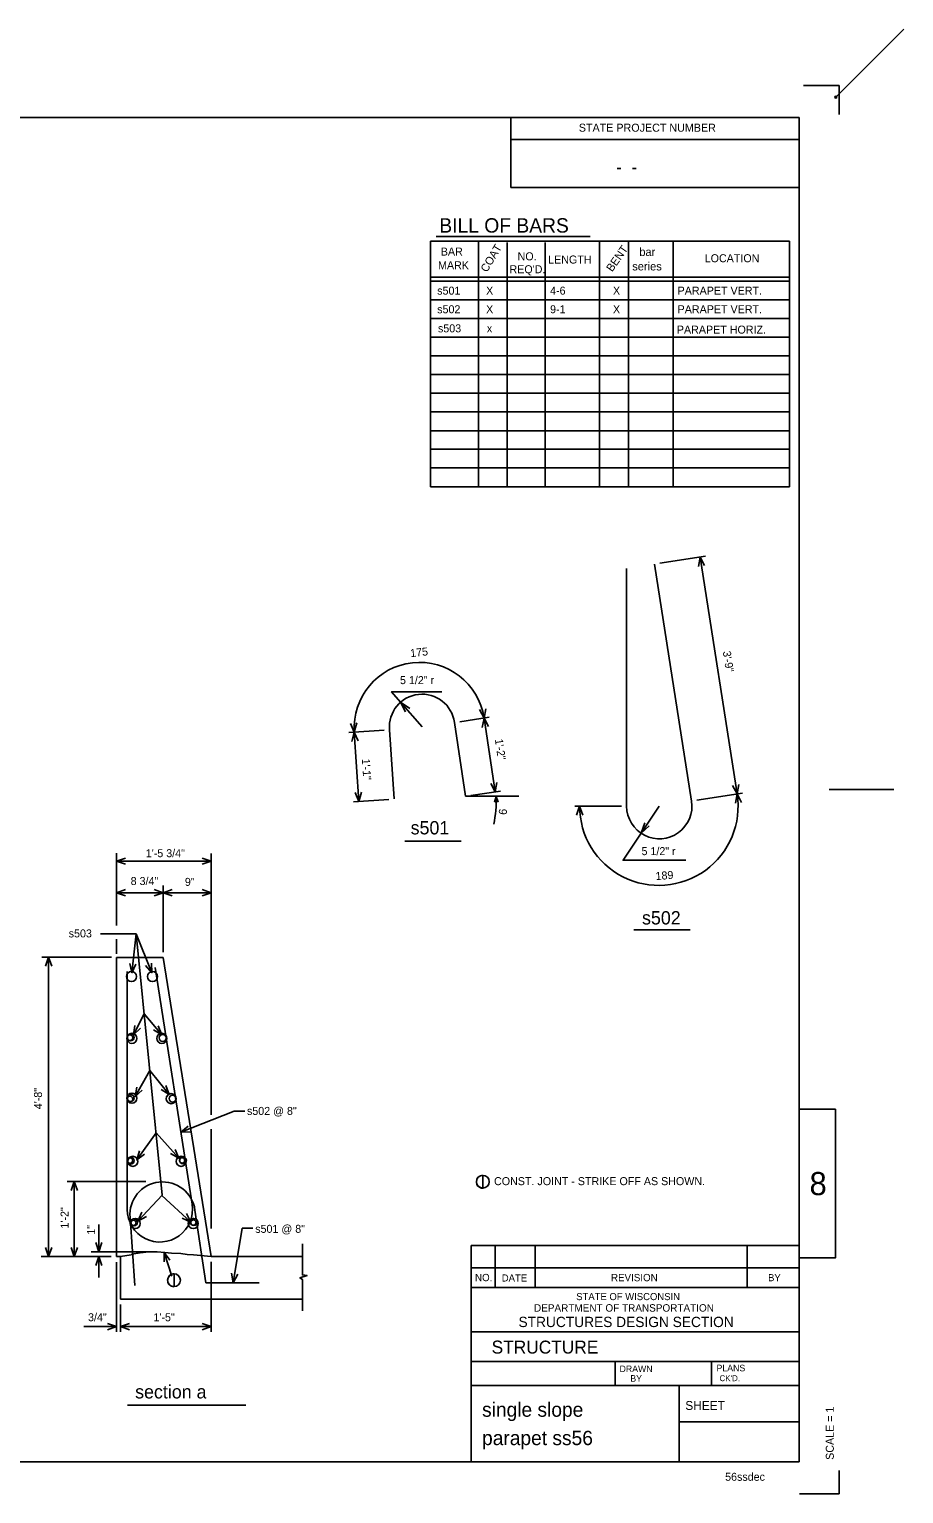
# Model space of a CAD drawing. Extents: x -38.4 to -2.2, y 84.9 to 109.4.
# Drawn here: x -15.84 to -2.17, y 85.97 to 108.85 of the extents above; entities that cross this region are included whole.
import ezdxf

# ---------------------------------------------------------------- set-up
doc = ezdxf.new("R2010")
doc.units = 0
for name, color, linetype in [('Default', 7, 'Continuous'), ('Level 1', 7, 'Continuous'), ('Level 2', 7, 'Continuous'), ('Level 37', 7, 'Continuous'), ('Level 49', 7, 'Continuous')]:
    doc.layers.add(name, color=color, linetype=linetype)

msp = doc.modelspace()

# ---------------------------------------------------------------- linework, layer by layer
at = {"layer": 'Default'}
for p, q in [((-14.473, 94.846), (-14.473, 95.978)), ((-14.473, 95.851), (-12.994, 95.851)), ((-12.994, 94.526), (-12.994, 95.97)), ((-13.744, 94.428), (-13.744, 95.471)), ((-14.473, 95.358), (-13.744, 95.358)), ((-13.744, 95.358), (-12.994, 95.358)), ((-14.168, 94.719), (-14.722, 94.719)), ((-14.232, 94.11), (-14.168, 94.719)), ((-14.168, 94.719), (-13.759, 90.637)), ((-14.168, 94.719), (-13.919, 94.11)), ((-12.994, 91.891), (-12.994, 94.809)), ((-14.473, 94.428), (-14.473, 94.634)), ((-14.473, 94.407), (-14.473, 94.617)), ((-14.55, 94.355), (-15.639, 94.355)), ((-15.533, 89.678), (-15.533, 94.355)), ((-14.473, 94.345), (-13.744, 94.345)), ((-14.473, 94.345), (-14.473, 89.678)), ((-12.994, 89.678), (-13.744, 94.345)), ((-14.304, 94.126), (-14.304, 90.412)), ((-13.291, 90.492), (-13.869, 94.193)), ((-14.206, 93.138), (-14.043, 93.469)), ((-14.043, 93.469), (-13.767, 93.138)), ((-14.181, 92.175), (-13.954, 92.581)), ((-13.954, 92.581), (-13.649, 92.209)), ((-12.633, 91.949), (-13.467, 91.617)), ((-12.466, 91.949), (-12.633, 91.949)), ((-14.156, 91.186), (-13.856, 91.609)), ((-13.856, 91.609), (-13.497, 91.212)), ((-12.994, 90.113), (-12.994, 91.664)), ((-14.017, 90.847), (-15.245, 90.847)), ((-15.133, 89.678), (-15.133, 90.847)), ((-8.748, 90.743), (-8.748, 90.943)), ((-8.748, 90.743), (-8.748, 90.943)), ((-13.759, 90.637), (-14.139, 90.231)), ((-13.311, 90.214), (-13.763, 90.632)), ((-13.078, 89.267), (-13.248, 90.4)), ((-14.75, 89.752), (-14.75, 90.178)), ((-14.189, 89.226), (-14.262, 90.286)), ((-12.509, 90.121), (-12.652, 89.267)), ((-12.342, 90.121), (-12.509, 90.121)), ((-14.557, 89.678), (-15.649, 89.678)), ((-15.213, 89.678), (-15.05, 89.678)), ((-13.943, 89.752), (-14.871, 89.752)), ((-14.75, 89.349), (-14.75, 89.678)), ((-14.473, 89.678), (-14.411, 89.678)), ((-14.411, 89.678), (-14.411, 89.011)), ((-13.611, 89.371), (-13.727, 89.741)), ((-11.568, 89.678), (-12.994, 89.678)), ((-14.473, 89.586), (-14.473, 88.498)), ((-12.994, 89.595), (-12.994, 88.498)), ((-13.573, 89.204), (-13.573, 89.405)), ((-13.078, 89.267), (-12.244, 89.267)), ((-14.411, 89.011), (-11.568, 89.011)), ((-14.411, 88.928), (-14.411, 88.498)), ((-14.473, 88.581), (-14.982, 88.581)), ((-14.411, 88.581), (-12.994, 88.581)), ((-14.302, 87.356), (-12.451, 87.356))]:
    msp.add_line(p, q, dxfattribs=at)
for points in [[(-14.333, 95.803), (-14.473, 95.851), (-14.333, 95.9)], [(-13.135, 95.9), (-12.994, 95.851), (-13.135, 95.803)], [(-14.333, 95.309), (-14.473, 95.358), (-14.333, 95.407)], [(-13.885, 95.407), (-13.744, 95.358), (-13.885, 95.309)], [(-13.603, 95.309), (-13.744, 95.358), (-13.603, 95.407)], [(-13.135, 95.407), (-12.994, 95.358), (-13.135, 95.309)], [(-15.582, 94.214), (-15.533, 94.355), (-15.484, 94.214)], [(-14.169, 94.245), (-14.232, 94.11), (-14.265, 94.256)], [(-13.927, 94.259), (-13.919, 94.11), (-14.018, 94.222)], [(-14.1, 93.243), (-14.206, 93.138), (-14.187, 93.286)], [(-13.82, 93.278), (-13.767, 93.138), (-13.895, 93.216)], [(-14.07, 92.274), (-14.181, 92.175), (-14.155, 92.322)], [(-13.7, 92.349), (-13.649, 92.209), (-13.776, 92.287)], [(-13.318, 91.624), (-13.467, 91.617), (-13.354, 91.714)], [(-14.035, 91.273), (-14.156, 91.186), (-14.114, 91.329)], [(-13.555, 91.349), (-13.497, 91.212), (-13.627, 91.284)], [(-15.182, 90.706), (-15.133, 90.847), (-15.084, 90.706)], [(-14.007, 90.301), (-14.139, 90.231), (-14.078, 90.367)], [(-13.381, 90.346), (-13.311, 90.214), (-13.447, 90.274)], [(-13.355, 90.297), (-13.311, 90.214), (-13.396, 90.252)], [(-15.484, 89.819), (-15.533, 89.678), (-15.582, 89.819)], [(-15.084, 89.819), (-15.133, 89.678), (-15.182, 89.819)], [(-14.701, 89.893), (-14.75, 89.752), (-14.798, 89.893)], [(-14.798, 89.537), (-14.75, 89.678), (-14.701, 89.537)], [(-14.411, 89.678), (-14.245, 89.7), (-14.233, 89.712), (-14.101, 89.734), (-13.966, 89.752), (-13.837, 89.749), (-13.717, 89.737), (-13.616, 89.728), (-13.469, 89.725), (-13.371, 89.71), (-13.269, 89.7), (-12.994, 89.678)], [(-13.731, 89.592), (-13.727, 89.741), (-13.638, 89.621)], [(-11.568, 88.826), (-11.568, 89.319), (-11.609, 89.341), (-11.497, 89.382), (-11.568, 89.388), (-11.568, 89.874)], [(-12.58, 89.398), (-12.652, 89.267), (-12.676, 89.414)], [(-14.614, 88.63), (-14.473, 88.581), (-14.614, 88.533)], [(-14.27, 88.533), (-14.411, 88.581), (-14.27, 88.63)], [(-13.135, 88.63), (-12.994, 88.581), (-13.135, 88.533)]]:
    msp.add_lwpolyline(points, dxfattribs=at)
for points in [[(-8.748, 90.744), (-8.748, 90.943), (-8.748, 90.944), (-8.767, 90.943), (-8.789, 90.937), (-8.807, 90.927), (-8.826, 90.91), (-8.837, 90.895), (-8.846, 90.874), (-8.851, 90.849), (-8.849, 90.825), (-8.844, 90.807), (-8.831, 90.783), (-8.818, 90.77), (-8.802, 90.757), (-8.785, 90.75), (-8.77, 90.746), (-8.762, 90.744)], [(-8.748, 90.744), (-8.748, 90.943), (-8.748, 90.944), (-8.767, 90.943), (-8.789, 90.937), (-8.807, 90.927), (-8.826, 90.91), (-8.837, 90.895), (-8.846, 90.874), (-8.851, 90.849), (-8.849, 90.825), (-8.844, 90.807), (-8.831, 90.783), (-8.818, 90.77), (-8.802, 90.757), (-8.785, 90.75), (-8.77, 90.746), (-8.762, 90.744)], [(-13.573, 89.205), (-13.573, 89.405), (-13.573, 89.405), (-13.592, 89.404), (-13.614, 89.399), (-13.632, 89.388), (-13.651, 89.372), (-13.662, 89.356), (-13.671, 89.335), (-13.676, 89.31), (-13.673, 89.286), (-13.669, 89.269), (-13.656, 89.245), (-13.643, 89.232), (-13.627, 89.219), (-13.61, 89.212), (-13.595, 89.207), (-13.586, 89.206)]]:
    msp.add_lwpolyline(points, close=True, dxfattribs=at)
for centre, radius in [((-14.239, 94.049), 0.0788), ((-13.91, 94.049), 0.0788), ((-14.232, 93.084), 0.0788), ((-14.253, 93.099), 0.0539), ((-14.262, 93.095), 0.0417), ((-13.764, 93.084), 0.0788), ((-13.752, 93.091), 0.0539), ((-14.232, 92.15), 0.0788), ((-14.253, 92.151), 0.0539), ((-13.618, 92.142), 0.0788), ((-13.598, 92.143), 0.0539), ((-14.262, 92.137), 0.0417), ((-14.253, 91.172), 0.0539), ((-14.262, 91.175), 0.0417), ((-14.217, 91.163), 0.0788), ((-13.464, 91.163), 0.0788), ((-13.436, 91.18), 0.0539), ((-13.447, 91.178), 0.0417), ((-8.75, 90.844), 0.1), ((-8.75, 90.844), 0.1), ((-14.18, 90.192), 0.0788), ((-14.199, 90.209), 0.0539), ((-14.208, 90.203), 0.0417), ((-13.274, 90.192), 0.0788), ((-13.266, 90.217), 0.0539), ((-13.272, 90.206), 0.0417), ((-13.575, 89.306), 0.1)]:
    msp.add_circle(centre, radius, dxfattribs=at)
for centre, start, end in [((-13.753, 90.332), 7.615, 185.2003), ((-13.795, 90.412), 180, 9)]:
    msp.add_arc(centre, 0.51, start, end, dxfattribs=at)
at = {"layer": 'Level 1'}
for p, q in [((-3.184, 107.971), (-3.739, 107.971)), ((-3.184, 107.516), (-3.184, 107.971)), ((-3.809, 107.471), (-35.185, 107.471)), ((-8.315, 107.471), (-8.315, 106.375)), ((-3.809, 86.471), (-3.809, 107.471)), ((-8.315, 107.126), (-3.809, 107.126)), ((-8.315, 106.375), (-3.809, 106.375)), ((-5.489, 96.791), (-6.068, 100.492)), ((-5.985, 100.505), (-5.274, 100.616)), ((-5.356, 100.603), (-4.778, 96.902)), ((-6.503, 100.425), (-6.503, 96.711)), ((-9.699, 97.951), (-10.034, 98.336)), ((-9.02, 96.865), (-9.193, 98.019)), ((-9.111, 98.031), (-8.649, 98.1)), ((-8.731, 98.088), (-8.558, 96.934)), ((-10.29, 97.899), (-10.842, 97.861)), ((-10.685, 96.786), (-10.758, 97.867)), ((-10.133, 96.824), (-10.207, 97.905)), ((-10.217, 96.818), (-10.768, 96.781)), ((-9.02, 96.865), (-8.187, 96.865)), ((-8.938, 96.877), (-8.476, 96.946)), ((-5.407, 96.804), (-4.695, 96.915)), ((-6.586, 96.711), (-7.313, 96.711)), ((-5.993, 96.711), (-6.277, 96.287)), ((-9.97, 96.166), (-9.091, 96.166)), ((-6.392, 94.779), (-5.513, 94.779)), ((-8.934, 89.846), (-3.806, 89.846)), ((-8.934, 89.19), (-8.934, 89.846)), ((-8.555, 89.19), (-8.555, 89.846)), ((-7.93, 89.19), (-7.93, 89.846)), ((-4.618, 89.19), (-4.618, 89.846)), ((-8.934, 89.502), (-3.806, 89.502)), ((-8.934, 86.471), (-8.934, 89.19)), ((-8.934, 89.19), (-3.806, 89.19)), ((-8.934, 88.502), (-3.806, 88.502)), ((-8.934, 88.034), (-3.806, 88.034)), ((-6.683, 87.659), (-6.683, 88.034)), ((-5.176, 87.659), (-5.176, 88.034)), ((-8.934, 87.659), (-3.806, 87.659)), ((-5.684, 86.471), (-5.684, 87.659)), ((-5.683, 87.096), (-3.809, 87.096)), ((-35.185, 86.471), (-3.809, 86.471)), ((-3.184, 85.971), (-3.184, 86.334)), ((-3.802, 85.971), (-3.184, 85.971))]:
    msp.add_line(p, q, dxfattribs=at)
for points in [[(-5.382, 100.456), (-5.356, 100.603), (-5.286, 100.471)], [(-10.034, 98.336), (-10.175, 98.499), (-9.388, 98.499)], [(-9.956, 98.183), (-10.034, 98.336), (-9.893, 98.238)], [(-8.704, 98.234), (-8.731, 98.088), (-8.8, 98.22)], [(-10.719, 98.011), (-10.758, 97.867), (-10.817, 98.004)], [(-8.758, 97.941), (-8.731, 98.088), (-8.662, 97.956)], [(-10.797, 97.723), (-10.758, 97.867), (-10.7, 97.73)], [(-8.531, 97.081), (-8.558, 96.934), (-8.627, 97.066)], [(-4.751, 97.049), (-4.778, 96.902), (-4.847, 97.034)], [(-10.646, 96.93), (-10.685, 96.786), (-10.743, 96.924)], [(-4.804, 96.756), (-4.778, 96.902), (-4.708, 96.771)], [(-7.286, 96.57), (-7.238, 96.711), (-7.189, 96.57)], [(-6.15, 96.402), (-6.277, 96.287), (-6.219, 96.449)], [(-6.277, 96.287), (-6.558, 95.866), (-5.579, 95.866)]]:
    msp.add_lwpolyline(points, dxfattribs=at)
msp.add_lwpolyline([(-3.809, 91.976), (-3.242, 91.976), (-3.242, 89.654), (-3.809, 89.654)], close=True, dxfattribs=at)
for centre, radius, start, end in [((-9.74, 97.937), 1.02, 8.5231, 183.9058), ((-9.699, 97.951), 0.51, 7.615, 185.2003), ((-6, 96.711), 1.238, 180, 8.8807), ((-5.993, 96.711), 0.51, 180, 9)]:
    msp.add_arc(centre, radius, start, end, dxfattribs=at)
at = {"layer": 'Level 2'}
for p, q in [((-3.235, 107.786), (-2.175, 108.847)), ((-9.568, 105.536), (-8.343, 105.536)), ((-9.568, 105.536), (-9.568, 101.702)), ((-9.48, 105.608), (-7.072, 105.608)), ((-8.818, 105.536), (-8.818, 101.702)), ((-8.368, 105.519), (-8.368, 101.702)), ((-8.343, 105.536), (-7.775, 105.536)), ((-7.775, 105.536), (-5.775, 105.536)), ((-7.775, 105.519), (-7.775, 101.702)), ((-6.925, 105.536), (-6.925, 101.702)), ((-6.475, 105.536), (-6.475, 101.702)), ((-5.775, 105.536), (-3.958, 105.536)), ((-5.775, 105.536), (-5.775, 101.702)), ((-3.958, 105.536), (-3.958, 101.702)), ((-9.568, 104.973), (-7.775, 104.973)), ((-9.568, 104.911), (-7.775, 104.911)), ((-7.775, 104.973), (-5.775, 104.973)), ((-7.775, 104.911), (-5.775, 104.911)), ((-5.775, 104.973), (-3.958, 104.973)), ((-5.775, 104.911), (-3.958, 104.911)), ((-9.568, 104.619), (-7.775, 104.619)), ((-7.775, 104.619), (-5.775, 104.619)), ((-5.775, 104.619), (-3.958, 104.619)), ((-9.568, 104.327), (-7.775, 104.327)), ((-7.775, 104.327), (-5.775, 104.327)), ((-5.775, 104.327), (-3.958, 104.327)), ((-9.568, 104.036), (-7.775, 104.036)), ((-7.775, 104.036), (-5.775, 104.036)), ((-5.775, 104.036), (-3.958, 104.036)), ((-9.568, 103.744), (-7.775, 103.744)), ((-7.775, 103.744), (-5.775, 103.744)), ((-5.775, 103.744), (-3.958, 103.744)), ((-9.568, 103.452), (-7.775, 103.452)), ((-7.775, 103.452), (-5.775, 103.452)), ((-5.775, 103.452), (-3.958, 103.452)), ((-9.568, 103.161), (-7.775, 103.161)), ((-7.775, 103.161), (-5.775, 103.161)), ((-5.775, 103.161), (-3.958, 103.161)), ((-9.568, 102.869), (-7.775, 102.869)), ((-7.775, 102.869), (-5.775, 102.869)), ((-5.775, 102.869), (-3.958, 102.869)), ((-9.568, 102.577), (-7.775, 102.577)), ((-7.775, 102.577), (-5.775, 102.577)), ((-5.775, 102.577), (-3.958, 102.577)), ((-9.568, 102.286), (-7.775, 102.286)), ((-7.775, 102.286), (-5.775, 102.286)), ((-5.775, 102.286), (-3.958, 102.286)), ((-9.568, 101.994), (-7.775, 101.994)), ((-7.775, 101.994), (-5.775, 101.994)), ((-5.775, 101.994), (-3.958, 101.994)), ((-9.568, 101.702), (-7.775, 101.702)), ((-9.568, 101.702), (-7.775, 101.702)), ((-7.775, 101.702), (-3.958, 101.702)), ((-7.775, 101.702), (-3.958, 101.702))]:
    msp.add_line(p, q, dxfattribs=at)
msp.add_lwpolyline([(-8.57, 96.774), (-8.543, 96.863), (-8.509, 96.776)], dxfattribs=at)
msp.add_arc((-10.254, 96.793), 1.713, 347.6879, 2.3357, dxfattribs=at)
at = {"layer": 'Level 37'}
msp.add_line((-3.339, 96.971), (-2.329, 96.971), dxfattribs=at)
at = {"layer": 'Level 49'}
msp.add_circle((-3.236, 107.786), 0.0152, dxfattribs=at)

# ---------------------------------------------------------------- texts
at = {"layer": 'Default'}
for s, height, p in [('1\'-5 3/4"', 0.125, (-14.016, 95.914)), ('8 3/4"', 0.125, (-14.252, 95.479)), ('9"', 0.125, (-13.405, 95.466)), ('s503', 0.125, (-15.22, 94.661)), ('s502 @ 8"', 0.125, (-12.435, 91.888)), ('CONST. JOINT - STRIKE OFF AS SHOWN.', 0.125, (-8.575, 90.791)), ('CONST. JOINT - STRIKE OFF AS SHOWN.', 0.125, (-8.575, 90.791)), ('s501 @ 8"', 0.125, (-12.306, 90.046)), ('3/4"', 0.125, (-14.918, 88.665)), ('1\'-5"', 0.125, (-13.896, 88.665)), ('section a', 0.2083, (-14.182, 87.459)), ('56ssdec', 0.125, (-4.965, 86.173))]:
    msp.add_text(s, height=height, dxfattribs=at).set_placement(p)
for s, p in [('4\'-8"', (-15.637, 91.977)), ('1\'-2"', (-15.222, 90.113)), ('1"', (-14.807, 90.016))]:
    msp.add_text(s, height=0.125, rotation=90, dxfattribs=at).set_placement(p)
at = {"layer": 'Level 1'}
for s, height, p in [('STATE PROJECT NUMBER', 0.12525, (-7.25, 107.247)), ('    -  -  ', 0.2023, (-6.969, 106.594)), ('5 1/2" r', 0.125, (-10.044, 98.618)), ('s501', 0.2083, (-9.878, 96.27)), ('5 1/2" r', 0.125, (-6.271, 95.946)), ('s502', 0.2083, (-6.263, 94.863)), ('8', 0.361, (-3.646, 90.635)), ('NO.', 0.1139, (-8.872, 89.291)), ('DATE', 0.1109, (-8.454, 89.286)), ('REVISION', 0.1142, (-6.748, 89.29)), ('BY', 0.1108, (-4.294, 89.29)), ('STATE OF WISCONSIN', 0.11076, (-7.291, 88.995)), ('DEPARTMENT OF TRANSPORTATION', 0.11643, (-7.951, 88.815)), ('STRUCTURES DESIGN SECTION', 0.1605, (-8.193, 88.574)), ('STRUCTURE', 0.2022, (-8.613, 88.16)), ('DRAWN', 0.1022, (-6.614, 87.871)), ('PLANS', 0.1023, (-5.099, 87.883)), ('BY', 0.102, (-6.446, 87.721)), ("CK'D.", 0.0927, (-5.052, 87.729)), (' single slope ', 0.22392, (-8.845, 87.173)), ('SHEET', 0.1387, (-5.587, 87.28)), (' parapet ss56 ', 0.22392, (-8.845, 86.73))]:
    msp.add_text(s, height=height, dxfattribs=at).set_placement(p)
for s, rotation, p in [('175', 6.2145, (-9.879, 99.038)), ('3\'-9"', 278.8807, (-5.002, 99.126)), ('1\'-2"', 278.5231, (-8.563, 97.754)), ('1\'-1"', 273.9058, (-10.64, 97.449)), ('189', 4.4403, (-6.047, 95.556)), ('SCALE = 1        ', 90, (-3.267, 86.5))]:
    msp.add_text(s, height=0.125, rotation=rotation, dxfattribs=at).set_placement(p)
at = {"layer": 'Level 2'}
for s, height, p in [('BILL OF BARS', 0.225, (-9.43, 105.671)), ('BAR', 0.125, (-9.407, 105.312)), ('NO.', 0.125, (-8.207, 105.238)), ('LENGTH', 0.125, (-7.73, 105.188)), ('bar', 0.1294, (-6.305, 105.305)), ('LOCATION', 0.125, (-5.284, 105.208)), ('MARK', 0.125, (-9.45, 105.098)), ("REQ'D.", 0.125, (-8.334, 105.036)), ('series', 0.1294, (-6.416, 105.08)), ('s501', 0.125, (-9.463, 104.702)), ('X', 0.125, (-8.699, 104.702)), (' 4-6 ', 0.125, (-7.746, 104.702)), ('X', 0.125, (-6.717, 104.702)), ('PARAPET VERT.   ', 0.125, (-5.707, 104.702)), ('s502', 0.125, (-9.463, 104.411)), ('X', 0.125, (-8.699, 104.411)), (' 9-1 ', 0.125, (-7.746, 104.411)), ('X', 0.125, (-6.717, 104.411)), ('PARAPET VERT.   ', 0.125, (-5.707, 104.411)), ('s503', 0.125, (-9.451, 104.113)), ('x', 0.125, (-8.687, 104.113)), ('PARAPET HORIZ.  ', 0.125, (-5.719, 104.093))]:
    msp.add_text(s, height=height, dxfattribs=at).set_placement(p)
for s, rotation, p in [('COAT', 59.0083, (-8.687, 105.041)), ('BENT', 54.9994, (-6.73, 105.049)), ('9', 265.9161, (-8.496, 96.675))]:
    msp.add_text(s, height=0.125, rotation=rotation, dxfattribs=at).set_placement(p)

doc.saveas('drawing.dxf')
